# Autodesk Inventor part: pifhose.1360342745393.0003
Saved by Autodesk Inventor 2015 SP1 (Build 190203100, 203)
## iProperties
IsCustomPart: 1
Company: Parker Hannifin
Created: 2013-02
Material: Rubber
Description: Tömlő
Document SubType Name: Modeling
Standard: Parker
Designer: Marci
Manufacturer: Parker
Language: hu-HU
Size Designation: 1/4 - 5
Categories: <MemberInstance><Categories><Category DisplayName="Csővezetékek" InternalName="4347fa0f-2144-441d-94cd-e3e15c92b736" Mnemonic="TUBEANDPIPE"><CategoryParameter D
Stock Number: Parker hidraulikatömlő - No Skive 1/4
Density: 1 g/cm^3
Appearance: Rubber - Black - Version 1.1
NAME: PIPING: Parker Hydraulic Hose - No Skive
DATA: <meta><inlinegroups number="1" deflen="12.7"></inlinegroups><connections number="2"></connections><angles><a>3.14159265358979</a></angles></meta>
L: 7,472 in
PL: 7,472 in
RPL: 7,500 in
OPL: 7,472 in
ROPL: 7,500 in
Author: Marci
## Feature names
1. Sweep1
## Parameters: ID = 6.35 mm, OD = 14.986 mm, L = 189.7888 mm, PL = 189.7888 mm, Size_Designation = 2.5 mm, d6 = 0, RPL = 190.5 mm, OPL = 189.7888 mm, ROPL = 190.5 mm, d7 = 0
